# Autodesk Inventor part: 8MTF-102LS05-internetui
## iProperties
Created: 2010-02
Part Number: 8MTF-102LS05-internetui
Document SubType Name: Modeling
Designer: Darius
Author: Darius
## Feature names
1. Base1
